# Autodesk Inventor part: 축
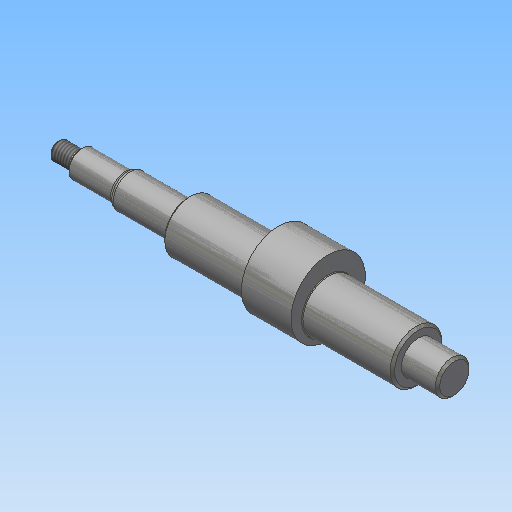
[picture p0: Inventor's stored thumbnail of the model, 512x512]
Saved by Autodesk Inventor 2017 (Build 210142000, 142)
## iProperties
Created: 2015-12
Part Number: 축
Document SubType Name: Modeling
Designer: mdu
Density: 7.86 g/cm^3
Material: 강철, 연강
Appearance: 강철
Mass: 489.93 g
Surface Area: 127.025 cm^2
Volume: 62.3321 cm^3
Author: mdu
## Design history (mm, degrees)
sketch "스케치1"
  geometry: L1 (62, 100.9)-(62, 67.1) reference; L2 (51, 101.2)-(51, 84) reference; L3 (-51, 84)-(-51, 101.2) reference; L4 (-62, 67.1)-(-62, 100.9) reference; L5 (-51.6, 91.5)-(-61.4, 91.5) reference; L6 (51.6, 91.5)-(61.4, 91.5) reference; L7 (67, 84)-(-109, 84); L8 (-77, 64.201)-(-77, 103.799) reference; L9 (67, 84)-(67, 91.5); L10 (67, 91.5)-(51, 91.5); L11 (51, 91.5)-(51, 95.5); L12 (51, 95.5)-(-51, 95.5); L13 (-51, 95.5)-(-51, 91.5); L14 (-51, 91.5)-(-79, 91.5); L15 (-79, 91.5)-(-79, 90); L16 (-79, 90)-(-99, 90); L17 (-99, 90)-(-99, 88); L18 (-99, 88)-(-109, 88); L19 (-109, 88)-(-109, 84); 2 further points
  constraints: 28 end point, 7 parallel, 5 point on line, 4 perpendicular, 2 collinear, 2 horizontal, 1 midpoint, 4 other
  dimensions: "d0" = 5 distance from line of L7.start L1; "d2" = 2 distance between parallel lines of L15 L8; "d3" = 23 diameter of L12 L7; "d4" = 12 diameter of L16 L7; "d7" = 20 distance of L15.end L16.end; "d8" = 10 distance between parallel lines of L17 L19; "d9" = 8 diameter of L18 L7
revolve "회전1" sketch "스케치1" stored, may be unused: angle "d10" = 90 deg
sketch "스케치2"
  geometry: C1 r 11.5 at (84, 0) reference; C2 r 11.5 at (84, 0) reference; C3 r 16.5 at (87, 0); 1 further point
  constraints: 1 centre point, 1 horizontal alignment
  dimensions: "d11" = 33 diameter of C3; "d12" = 3 distance of C3.centre C1.centre
extrude "돌출1" join sketch "스케치2" stored distance "d13" = 22; taper "d14" = 0 deg
chamfer "모따기1" distance "d15" = 1; stored, may be unused: second distance "d16" = 2, angle "d17" = 45 deg
feature "스레드1" dims "d18" = 8, "d19" = 0
node "작업 평면1"
sketch "스케치3"
  geometry: L1 (-5, -2)-(3, -2); L2 (3, 2)-(-5, 2); L3 (-10, -5)-(-10, 5) reference; A1 r 2 centre (3, 0) between (3, -2) and (3, 2); A2 r 2 centre (-5, 0) between (-5, 2) and (-5, -2); 2 further points
  constraints: 4 end point, 4 point on circle, 4 tangent, 2 centre point, 1 horizontal, 1 horizontal alignment, 1 midpoint, 1 parallel
  dimensions: "d20" = 4 distance between parallel lines of L1 L2; "d21" = 12 dimension on A1 A2; "d22" = 3 distance edge to line of A2 L3
extrude "돌출2" cut sketch "스케치3" distance "d23" = 2.5; taper "d24" = 0 deg
fillet "모깎기1" dims "d25" = 0.3
chamfer "모따기2" distance "d27" = 1.65; stored, may be unused: second distance "d28" = 2, angle "d29" = 30 deg
fillet "모깎기3" dims "d30" = 2
node "솔리드1"
node "참조1"
node "참조2"
node "참조3"
node "참조4"
node "참조5"
node "투영된 루프1"
